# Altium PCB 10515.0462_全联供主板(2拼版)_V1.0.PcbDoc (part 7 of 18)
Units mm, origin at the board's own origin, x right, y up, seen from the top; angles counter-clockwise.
Board outline 282 x 198 mm, 2 copper layers (Top Layer, Bottom Layer); 716 components, 0 nets, 2364 pads, 1800 vias.
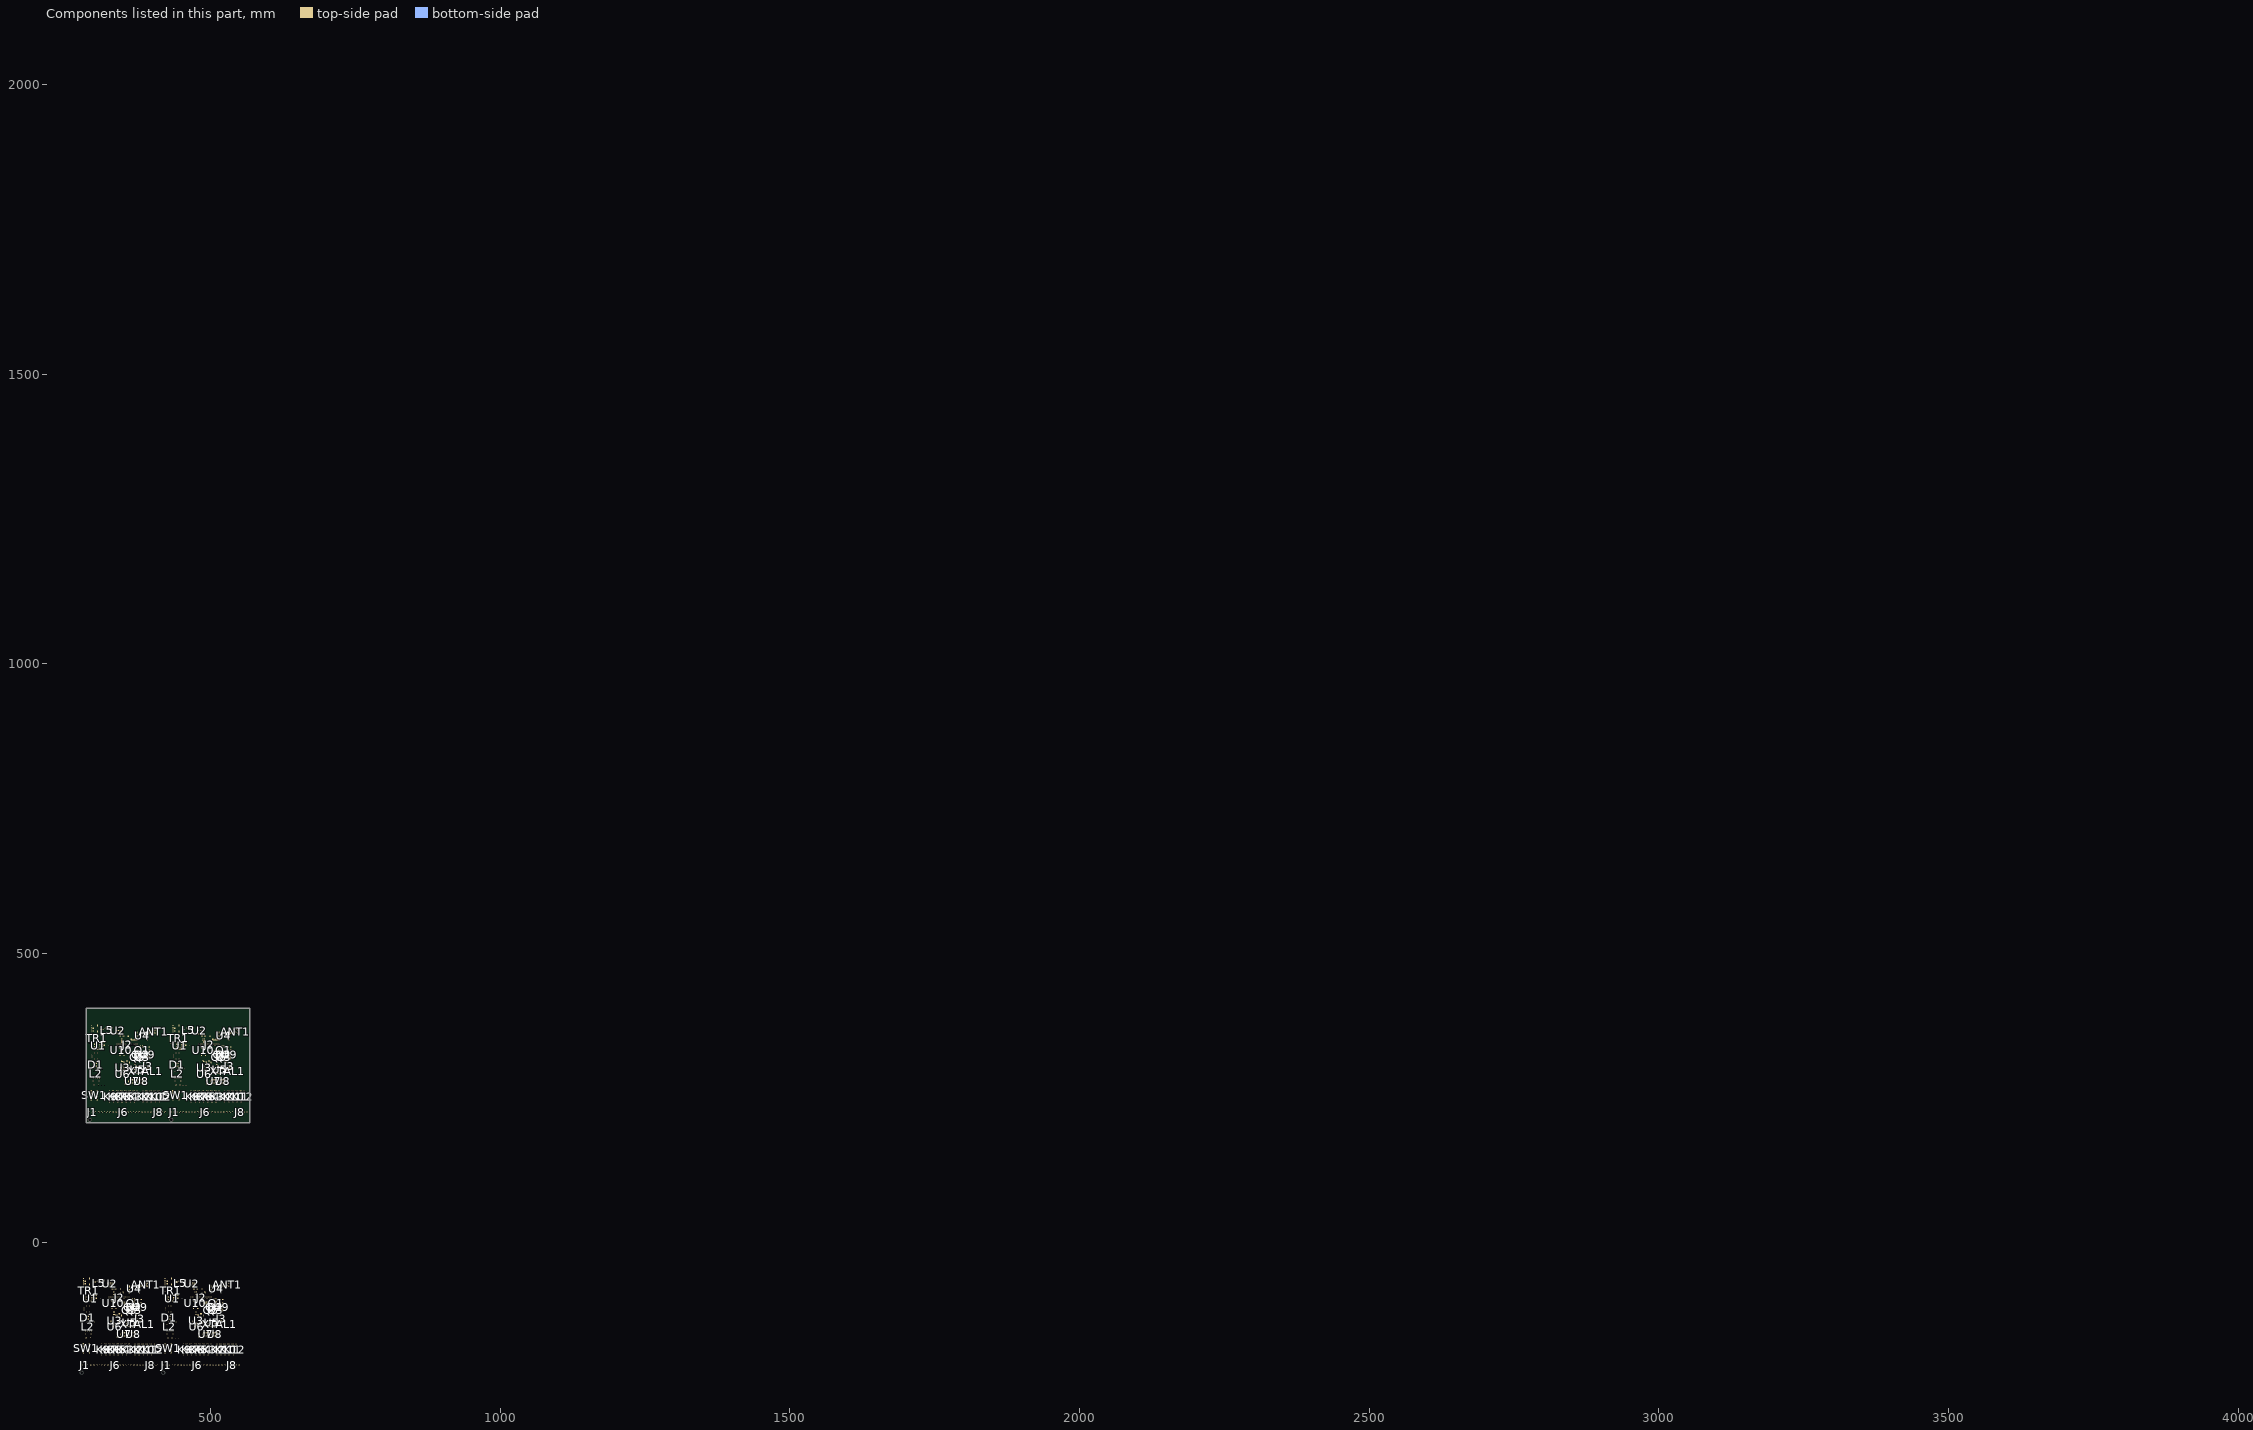
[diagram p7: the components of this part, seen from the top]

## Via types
v1: diameter 0.7, hole 0.4, Top Layer to Bottom Layer, tented both sides, 1800 vias

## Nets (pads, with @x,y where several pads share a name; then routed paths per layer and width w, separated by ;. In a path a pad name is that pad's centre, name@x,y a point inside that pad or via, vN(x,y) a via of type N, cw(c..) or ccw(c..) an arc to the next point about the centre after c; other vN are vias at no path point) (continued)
copper on no net: (continued)
  Top Layer w0.45: 390.197,261.97 390.197,263.712 ; 390.322,-173.798 ccw(c389.169,-172.645) 390.799,-172.645 ccw(c392.429,-172.645) 391.276,-173.798 ; v1@390.329,296.908 cw(c390.034,296.613) 390.452,296.613 ; 390.506,319.548 ccw(c389.632,320.423) v1@390.868,320.423 ; 390.592,304.283 ccw(c390.12,304.755) 390.676,305.125 ; 390.615,262.851 cw(c391.294,263.712) 390.197,263.712 ; 390.634,319.382 390.868,319.616 v1(390.868,320.491) 390.868,322.246 ; 390.672,331.157 ccw(c390.363,331.467) 390.801,331.467 ccw(c391.239,331.467) 390.929,331.157 ; 390.709,301.341 cw(c390.709,300.773) 391.111,301.175 ; 390.71,330.901 cw(c390.329,330.52) 390.868,330.52 ; 390.801,331.029 390.801,338.143 390.545,338.398 ; 390.868,328.342 390.868,330.961 ; v1@390.937,320.594 392.138,320.594 392.138,322.246 ; v1@390.957,320.403 cw(c391.419,319.941) 391.419,320.594 ; 391.047,302.632 cw(c390.406,301.992) 391.312,301.992 cw(c392.217,301.992) 391.577,302.632 ; 391.187,301.431 ccw(c390.886,301.732) 391.312,301.732 ; 391.277,301.303 391.312,301.338 ; 391.312,301.75 ccw(c391.762,301.75) 391.444,301.431 ; 391.312,302.838 391.312,301.338 ; 392.005,336.938 ccw(c390.386,338.558) 392.675,338.631 ; 392.183,319.382 393.731,319.382 ; 392.196,331.157 ccw(c391.887,331.467) 392.325,331.467 ccw(c392.763,331.467) 392.453,331.157 ; 392.311,319.254 cw(c392.621,318.944) 392.621,319.382 cw(c392.621,319.82) 392.311,319.51 ; 392.325,331.029 392.325,331.793 391.815,332.302 391.815,336.747 393.72,338.652 ; 392.74,337.673 ccw(c391.809,338.603) 393.125,338.646 ; 392.856,337.788 cw(c393.339,337.305) 393.339,337.988 ; 392.923,339.17 ccw(c392.012,340.303) 393.466,340.303 ; 392.928,301.303 393.318,301.303 394.912,302.897 394.912,305.078 395.144,305.31 ; 392.966,301.484 ccw(c392.966,302.771) 393.876,301.861 ; 393.303,333.969 ccw(c392.597,334.842) v1(393.72,334.842) ccw(c394.843,334.842) 394.137,333.969 ; 393.408,319.44 393.408,322.246 ; 393.408,320.638 ccw(c394.949,320.638) 393.86,319.548 ; 393.408,324.539 v1(393.408,326.841) ; 393.466,339.949 ccw(c394.635,339.949) 393.808,339.122 ; 393.603,319.254 ccw(c393.293,318.944) 393.293,319.382 ccw(c393.293,319.82) 393.603,319.51 ; 393.72,333.452 v1(393.72,334.842) ; 393.885,330.901 cw(c392.445,329.461) 394.482,329.461 ; 393.93,301.915 ccw(c392.949,302.897) 394.337,302.897 ; 393.976,331.029 394.482,330.523 394.482,326.206 v1(394.228,325.952) ; 394.003,330.848 cw(c393.972,330.339) 394.482,330.339 ; v1@394.139,326.041 ccw(c393.313,326.867) 394.482,326.867 ; 394.195,331.029 ccw(c394.725,331.029) 394.35,330.654 ; 394.204,331.219 cw(c393.532,330.547) 394.482,330.547 ; 394.647,303.162 ccw(c394.006,303.802) 394.912,303.802 ccw(c395.817,303.802) 395.177,303.162 ; 394.746,305.039 cw(c394.346,304.639) 394.912,304.639 ; 394.912,303.519 cw(c397.062,303.519) 395.541,305.039 ; 394.912,304.606 cw(c395.975,304.606) 395.223,305.358 ; 395.042,364.82 395.208,364.654 401.201,364.654 ; 395.311,364.538 cw(c395.59,364.259) 395.59,364.654 ; 395.311,364.795 ccw(c395.651,365.135) 395.651,364.654 ; 396.865,262.823 ccw(c395.961,263.832) 397.316,263.832 ; 397.316,261.97 397.316,263.832 ; 397.561,-173.798 ccw(c396.408,-172.645) 398.038,-172.645 ccw(c399.668,-172.645) 398.515,-173.798 ; 397.605,361.399 ccw(c396.26,360.49) v1@396.26,362.114 ; 397.605,362.828 cw(c396.26,363.738) v1@396.26,362.114 ; 397.766,262.823 cw(c398.671,263.832) 397.316,263.832 ; 397.978,361.651 ccw(c397.108,361.063) 397.108,362.114 ccw(c397.108,363.164) 397.978,362.576 ; 398.546,362.114 v1@396.26,362.114 ; 400.371,363.823 ccw(c398.365,361.817) 398.365,364.654 ccw(c398.365,367.49) 400.371,365.484 ; 400.689,364.141 ccw(c399.451,362.903) 399.451,364.654 ccw(c399.451,366.404) 400.689,365.166 ; 403.95,262.798 ccw(c402.798,263.95) 404.428,263.95 ccw(c406.057,263.95) 404.905,262.798 ; 411.189,262.798 ccw(c410.037,263.95) 411.667,263.95 ccw(c413.296,263.95) 412.144,262.798 ; 430.059,-97.823 430.059,-97.562 ; 430.059,-95.283 430.059,-94.895 ; 431.415,-99.768 ccw(c431.263,-99.478) 431.59,-99.478 ; 431.59,-100.099 431.59,-99.478 ; 431.677,-100.099 cw(c433.386,-100.099) 432.178,-98.891 ; 431.765,-99.768 cw(c431.917,-99.478) 431.59,-99.478 ; 432.127,-100.099 cw(c434.923,-100.099) 432.946,-98.123 ; 433.576,-99.834 ccw(c432.851,-99.11) 433.876,-99.11 ; 433.876,-99.972 433.876,-96.049 434.642,-95.283 436.155,-95.283 438.071,-95.283 438.448,-94.906 438.448,-93.763 439.464,-92.747 ; 433.876,-99.279 ccw(c434.662,-99.279) 434.106,-99.834 ; 436.155,-97.823 439.976,-97.823 ; 436.155,-94.013 433.753,-94.013 432.987,-94.779 432.987,-98.081 431.59,-99.478 ; 436.375,-90.056 ccw(c437.32,-89.112) 437.32,-90.447 ; 436.693,-89.738 ccw(c438.406,-88.025) 438.406,-90.447 ; 437.012,-89.42 ccw(c439.492,-86.939) 439.492,-90.447 ; 437.226,-90.447 440.48,-90.447 443.209,-90.447 ; 438.196,-97.823 ccw(c438.196,-95.198) 440.053,-97.054 ; 439.283,-97.823 ccw(c439.283,-96.284) 440.371,-97.372 ; 440.042,-93.001 ccw(c439.464,-93.532) 439.464,-92.747 ; 440.042,-92.494 cw(c439.464,-91.963) 439.464,-92.747 ; 440.053,-90.713 ccw(c439.413,-91.353) 439.413,-90.447 ccw(c439.413,-89.542) 440.053,-90.182 ; 440.48,-92.747 439.464,-92.747 ; 440.632,-90.447 ccw(c440.632,-87.582) 442.658,-89.608 ; 440.907,-90.713 cw(c441.547,-91.353) 441.547,-90.447 cw(c441.547,-89.542) 440.907,-90.182 ; 441.356,-90.447 cw(c441.356,-92.29) 442.658,-90.987 ; 441.494,-90.447 cw(c441.494,-92.639) 443.119,-91.169 ; 441.719,-90.447 ccw(c441.719,-88.668) 442.977,-89.926 ; 442.047,-90.447 ccw(c442.047,-89.355) 442.819,-90.128 ; v1(442.986,-81.687) 444.002,-82.703 445.78,-82.703 ; v1@443.191,-81.892 ccw(c443.621,-81.462) v1@443.621,-82.07 ; 443.494,-80.544 442.859,-80.544 442.605,-80.798 442.605,-82.068 443.24,-82.703 445.78,-82.703 ; 443.688,338.772 443.688,339.033 ; 443.688,341.312 443.688,341.7 ; v1@443.746,-82.195 ccw(c444.354,-82.195) 443.924,-82.625 ; 445.044,336.828 ccw(c444.892,337.117) 445.219,337.117 ccw(c445.545,337.117) 445.393,336.828 ; 445.219,336.496 445.219,337.117 446.616,338.514 446.616,341.816 447.382,342.582 449.784,342.582 ; 445.306,336.496 cw(c447.015,336.496) 445.806,337.705 ; 445.756,336.496 cw(c448.551,336.496) 446.575,338.473 ; 447.205,336.761 ccw(c446.48,337.486) 447.505,337.486 ; 447.505,336.623 447.505,340.546 448.271,341.312 449.784,341.312 451.7,341.312 452.077,341.689 452.077,342.832 453.093,343.848 ; 447.505,337.317 ccw(c448.291,337.317) 447.735,336.761 ; 449.784,338.772 453.605,338.772 ; 450.004,346.539 ccw(c450.948,347.484) 450.948,346.148 ; 450.322,346.857 ccw(c452.035,348.57) 452.035,346.148 ; 450.64,347.176 ccw(c453.121,349.656) 453.121,346.148 ; 450.855,346.148 454.109,346.148 456.838,346.148 ; 451.825,338.772 ccw(c451.825,341.398) 453.682,339.541 ; 452.194,-173.925 ccw(c451.041,-172.772) 452.671,-172.772 ccw(c454.301,-172.772) 453.148,-173.925 ; 452.671,-174.752 452.671,-172.123 455.72,-169.074 487.978,-169.074 488.613,-168.439 488.613,-166.153 488.613,-160.438 ; 452.912,338.772 ccw(c452.912,340.311) 454,339.223 ; 453.671,343.594 ccw(c453.093,343.063) 453.093,343.848 ; 453.671,344.102 cw(c453.093,344.633) 453.093,343.848 ; 453.682,345.883 ccw(c453.041,345.243) 453.041,346.148 ccw(c453.041,347.053) 453.682,346.413 ; 454.109,343.848 453.093,343.848 ; 454.261,346.148 ccw(c454.261,349.013) 456.287,346.987 ; 454.536,345.883 cw(c455.176,345.243) 455.176,346.148 cw(c455.176,347.053) 454.536,346.413 ; 454.985,346.148 cw(c454.985,344.306) 456.287,345.608 ; 455.123,346.148 cw(c455.123,343.956) 456.748,345.426 ; 455.348,346.148 ccw(c455.348,347.927) 456.605,346.669 ; 455.676,346.148 ccw(c455.676,347.24) 456.448,346.468 ; v1(456.615,354.908) 457.631,353.892 459.409,353.892 ; v1@456.82,354.704 ccw(c457.25,355.134) v1@457.25,354.525 ; 457.083,-83.846 455.94,-82.703 445.78,-82.703 ; 457.123,356.051 456.488,356.051 456.234,355.797 456.234,354.527 456.869,353.892 459.409,353.892 ; v1@457.375,354.4 ccw(c457.983,354.4) 457.553,353.97 ; 459.379,-173.925 ccw(c458.227,-172.772) 459.856,-172.772 ccw(c461.486,-172.772) 460.334,-173.925 ; 459.856,-174.752 459.856,-172.05 462.1,-169.806 488.897,-169.806 489.883,-168.82 489.883,-166.534 489.883,-160.438 ; 461.995,-71.781 462.544,-71.781 ; 462.29,-72.035 462.544,-71.781 ; 462.544,-71.831 cw(c463.391,-71.831) 462.932,-71.119 ; 462.63,-67.78 cw(c462.139,-68.272) 462.834,-68.272 ; 462.706,-69.111 ccw(c462.396,-68.802) 462.834,-68.802 ccw(c463.272,-68.802) 462.962,-69.111 ; 462.834,-71.781 462.925,-71.781 ; 462.834,-67.666 462.834,-69.278 463.198,-69.642 465.458,-69.642 ; 462.847,-70.942 465.458,-70.942 ; 462.962,-70.801 ccw(c463.304,-70.459) 463.304,-70.942 ; 462.962,-69.188 ccw(c464.06,-68.09) 464.06,-69.642 ; 462.979,-70.857 ccw(c463.814,-70.225) v1@463.814,-71.273 ; 463.772,-70.942 ccw(c463.772,-70.469) v1@464.107,-70.804 ; v1@464.08,-70.844 cw(c463.433,-70.571) 463.433,-71.273 ; v1(464.195,-70.892) v1@463.814,-71.273 ; v1@464.284,-70.804 ccw(c464.618,-70.469) 464.618,-70.942 ; 464.436,-67.717 v1(465.211,-67.717) ; 464.538,-67.524 ccw(c465.004,-67.058) v1@465.004,-67.717 ; 464.713,-72.76 cw(c464.403,-73.07) 464.841,-73.07 cw(c465.279,-73.07) 464.97,-72.76 ; 464.841,-75.022 ccw(c465.32,-75.022) 465.073,-75.432 ; 464.841,-74.225 ccw(c465.8,-74.225) 465.305,-75.047 ; 464.841,-73.429 ccw(c466.28,-73.429) 465.538,-74.661 ; 465.36,-96.285 cw(c464.93,-97.235) 465.973,-97.235 ; 465.499,-75.475 464.841,-74.818 464.841,-72.632 ccw(c466.76,-72.632) 465.77,-74.276 ; 465.545,-95.875 cw(c465.245,-96.538) 465.973,-96.538 ; 465.822,262.671 ccw(c464.67,263.823) 466.3,263.823 ccw(c467.929,263.823) 466.777,262.671 ; 465.973,-96.188 465.973,-97.181 ; 466.3,261.843 466.3,264.472 469.349,267.521 501.607,267.521 502.242,268.156 502.242,270.442 502.242,276.157 ; 466.474,-96.565 cw(c468.121,-98.212) 468.121,-95.882 ; 466.492,-72.632 467.901,-72.632 ; 466.539,-173.925 ccw(c465.386,-172.772) 467.016,-172.772 ccw(c468.645,-172.772) 467.493,-173.925 ; 466.659,-72.76 cw(c466.968,-73.07) 466.968,-72.632 cw(c466.968,-72.194) 466.659,-72.504 ; 466.804,-96.234 cw(c467.304,-96.735) 467.769,-96.201 ; 466.989,-129.312 465.973,-128.296 465.973,-97.181 ; 467.016,-174.752 467.016,-172.257 468.816,-170.456 490.025,-170.456 491.153,-169.328 491.153,-167.042 491.153,-160.438 ; 467.145,-95.893 cw(c467.622,-96.37) 468.064,-95.861 ; 467.242,-95.797 cw(c468.121,-96.675) 468.121,-95.432 ; 467.243,-95.795 465.973,-97.065 465.973,-97.181 ; 467.387,-72.632 ccw(c467.387,-72.102) 467.761,-72.477 ; 468.243,-136.468 469.848,-136.468 470.123,-136.193 v1(470.672,-136.193) ; 468.243,-134.817 469.786,-134.817 ; 468.371,-136.596 cw(c468.681,-136.906) 468.681,-136.468 cw(c468.681,-136.03) 468.371,-136.34 ; 468.371,-134.945 cw(c468.681,-135.255) 468.681,-134.817 cw(c468.681,-134.379) 468.371,-134.689 ; 469.362,-136.468 ccw(c469.362,-136.006) 469.689,-136.333 ; 469.362,-134.817 ccw(c469.362,-134.355) 469.689,-134.682 ; 469.396,-136.468 cw(c469.396,-136.882) 469.689,-136.589 ; 469.396,-134.817 cw(c469.396,-135.231) 469.689,-134.938 ; v1(469.656,-68.987) 470.412,-68.987 ; 469.849,-136.467 cw(c470.357,-136.975) v1@470.625,-136.309 ; 469.892,-134.923 472.294,-134.923 474.273,-134.923 474.58,-135.229 474.58,-138.086 ; v1@469.899,-68.987 cw(c469.899,-69.7) 470.403,-69.196 ; 469.945,-134.758 ccw(c470.343,-134.36) 470.343,-134.923 ; 469.966,-136.564 cw(c470.672,-137.049) v1(470.672,-136.193) ; 470.329,-145.584 472.364,-145.584 ; 470.448,-144.314 472.364,-144.314 478.46,-144.314 ; 470.452,-132.887 cw(c471.072,-132.887) v1@470.634,-132.448 ; v1@470.634,-132.272 ccw(c470.902,-132.004) 470.902,-132.383 ; 470.661,-92.718 ccw(c470.661,-91.422) 471.578,-92.339 ccw(c472.494,-93.255) 471.198,-93.255 cw(c473.722,-93.255) 471.937,-91.471 ; 470.712,352.749 469.569,353.892 459.409,353.892 ; 470.748,-93.255 cw(c472.185,-93.255) 471.169,-92.239 ; 471.561,-91.466 472.654,-90.373 473.238,-90.373 472.145,-91.466 ; 471.942,-91.466 470.661,-92.747 470.661,-93.255 472.45,-91.466 ; 471.959,-91.068 cw(c473.199,-92.309) 473.199,-90.554 ; 472.294,-136.193 v1(470.672,-136.193) ; 472.294,-133.653 470.463,-133.653 470.452,-133.641 470.452,-132.394 470.463,-132.383 472.294,-132.383 ; 472.364,-146.854 470.456,-146.854 470.325,-146.722 470.325,-143.42 470.702,-143.044 472.364,-143.044 474.258,-143.044 474.516,-142.785 474.516,-141.515 474.516,-140.708 474.736,-140.488 v1(477.403,-140.488) ; 472.381,-90.646 cw(c472.824,-91.089) 473.115,-90.534 ; 472.727,-90.3 cw(c473.199,-90.772) 473.199,-90.104 ; 472.863,-90.748 ccw(c472.488,-90.373) 473.018,-90.373 ; 473.008,262.671 ccw(c471.855,263.823) 473.485,263.823 ccw(c475.115,263.823) 473.962,262.671 ; 473.071,-90.501 ccw(c472.761,-90.811) 472.761,-90.373 ccw(c472.761,-89.935) 473.071,-90.245 ; 473.485,261.843 473.485,264.545 475.729,266.789 502.526,266.789 503.512,267.775 503.512,270.061 503.512,276.157 ; 473.786,-173.851 ccw(c473.253,-173.098) 474.175,-173.098 ; 474.175,-174.752 474.175,-173.098 ; 474.362,-131.053 cw(c474.053,-131.362) 474.491,-131.362 cw(c474.929,-131.362) 474.619,-131.053 ; 474.388,-141.644 cw(c474.078,-141.953) 474.516,-141.953 cw(c474.954,-141.953) 474.644,-141.644 ; 474.388,-141.387 ccw(c474.078,-141.077) 474.516,-141.077 ccw(c474.954,-141.077) 474.644,-141.387 ; 474.451,-137.958 ccw(c474.142,-137.648) 474.58,-137.648 ccw(c475.017,-137.648) 474.708,-137.958 ; v1(474.491,-134.13) 474.491,-131.051 ; 474.565,-173.851 cw(c475.098,-173.098) 474.175,-173.098 ; 475.624,364.814 476.173,364.814 ; 475.919,364.56 476.173,364.814 ; 476.013,-131.053 cw(c475.724,-131.342) 476.133,-131.342 ; 476.039,-141.644 cw(c475.729,-141.953) 476.167,-141.953 cw(c476.605,-141.953) 476.295,-141.644 ; 476.102,-137.958 ccw(c475.793,-137.648) 476.231,-137.648 ccw(c476.668,-137.648) 476.359,-137.958 ; 476.133,-131.383 cw(c476.6,-131.383) 476.27,-131.053 ; 476.133,-131.09 476.133,-131.957 476.559,-132.383 478.39,-132.383 ; 476.173,364.764 cw(c477.019,364.764) 476.561,365.476 ; 476.231,-138.086 476.231,-134.086 476.664,-133.653 478.39,-133.653 480.537,-133.653 480.993,-133.197 ; 476.259,368.815 cw(c475.767,368.323) 476.463,368.323 ; 476.333,-141.644 cw(c476.643,-141.953) 476.643,-141.515 cw(c476.643,-141.077) 476.333,-141.387 ; 476.335,367.484 ccw(c476.025,367.794) 476.463,367.794 ccw(c476.901,367.794) 476.591,367.484 ; 476.463,364.814 476.554,364.814 ; 476.463,368.93 476.463,367.318 476.827,366.953 479.087,366.953 ; 476.476,365.653 479.087,365.653 ; 476.591,365.795 ccw(c476.933,366.137) 476.933,365.653 ; 476.591,367.408 ccw(c477.688,368.505) 477.688,366.953 ; 476.607,365.738 ccw(c477.443,366.37) v1@477.443,365.322 ; 477.401,365.653 ccw(c477.401,366.127) v1@477.736,365.792 ; v1(477.694,-138.112) 481.07,-138.112 485.642,-138.112 ; v1@477.709,365.752 cw(c477.062,366.024) 477.062,365.322 ; v1(477.773,-141.515) 476.167,-141.515 476.167,-142.785 476.425,-143.044 478.46,-143.044 ; v1(477.824,365.703) v1@477.443,365.322 ; v1@477.912,365.792 ccw(c478.247,366.127) 478.247,365.653 ; 478.065,368.878 v1(478.84,368.878) ; 478.167,369.072 ccw(c478.633,369.538) v1@478.633,368.878 ; 478.342,363.835 cw(c478.032,363.525) 478.47,363.525 cw(c478.908,363.525) 478.598,363.835 ; 478.39,-136.193 480.853,-136.193 481.095,-136.435 482.517,-136.435 ; 478.39,-134.923 482.442,-134.923 482.517,-134.848 ; 478.47,361.574 ccw(c478.949,361.574) 478.702,361.163 ; 478.47,362.37 ccw(c479.429,362.37) 478.934,361.549 ; 478.47,363.167 ccw(c479.909,363.167) 479.166,361.934 ; 478.988,340.311 cw(c478.559,339.36) 479.602,339.36 ; 479.128,361.12 478.47,361.778 478.47,363.963 ccw(c480.389,363.963) 479.399,362.32 ; 479.174,340.721 cw(c478.874,340.058) 479.602,340.058 ; 479.547,-133.653 ccw(c479.547,-131.789) 480.865,-133.107 ; 479.602,340.408 479.602,339.414 ; 480.077,-136.193 cw(c480.077,-137.416) 480.942,-136.551 ; 480.103,340.031 cw(c481.75,338.384) 481.75,340.713 ; 480.121,363.963 481.529,363.963 ; 480.167,262.671 ccw(c479.015,263.823) 480.645,263.823 ccw(c482.274,263.823) 481.122,262.671 ; 480.288,363.835 cw(c480.597,363.525) 480.597,363.963 cw(c480.597,364.401) 480.288,364.092 ; 480.433,340.361 cw(c480.933,339.861) 481.397,340.395 ; 480.467,-134.923 ccw(c480.467,-134.36) 480.865,-134.758 ; 480.618,307.283 479.602,308.299 479.602,339.414 ; 480.618,-133.572 cw(c480.993,-133.946) 480.993,-133.416 ; 480.633,-133.653 ccw(c480.633,-132.875) 481.183,-133.425 ; 480.645,261.843 480.645,264.339 482.445,266.139 503.654,266.139 504.782,267.267 504.782,269.553 504.782,276.157 ; 480.774,340.702 cw(c481.251,340.226) 481.693,340.734 ; 480.871,340.799 cw(c481.75,339.92) 481.75,341.163 ; 480.872,340.8 479.602,339.53 479.602,339.414 ; 480.942,-138.24 ccw(c480.632,-138.55) 480.632,-138.112 ccw(c480.632,-137.674) 480.942,-137.984 ; 481.015,363.963 ccw(c481.015,364.493) 481.39,364.119 ; 481.111,-174.417 cw(c482.424,-174.331) 481.493,-173.4 ; 481.121,-134.758 ccw(c481.519,-134.36) 481.519,-134.923 ; 481.198,-138.24 cw(c481.508,-138.55) 481.508,-138.112 cw(c481.508,-137.674) 481.198,-137.984 ; 481.198,-136.551 cw(c481.477,-136.83) 481.477,-136.435 ; 481.198,-136.294 ccw(c481.539,-135.954) 481.539,-136.435 ; 481.335,-174.752 481.335,-173.558 482.898,-171.995 492.169,-171.995 493.693,-170.471 493.693,-168.185 493.693,-160.438 ; 481.56,-174.387 cw(c483.742,-174.244) 482.196,-172.698 ; 481.872,300.128 483.477,300.128 483.752,300.403 v1(484.301,300.403) ; 481.872,301.779 483.415,301.779 ; 481.991,-134.923 ccw(c481.991,-134.36) 482.389,-134.758 ; 482,299.999 cw(c482.31,299.69) 482.31,300.128 cw(c482.31,300.566) 482,300.256 ; 482,301.65 cw(c482.31,301.341) 482.31,301.779 cw(c482.31,302.217) 482,301.907 ; 482.009,-174.358 cw(c485.06,-174.158) 482.898,-171.996 ; 482.351,-136.564 ccw(c482.041,-136.873) 482.041,-136.435 ccw(c482.041,-135.997) 482.351,-136.307 ; 482.517,-133.197 v1(483.447,-133.197) ; 482.645,-133.325 cw(c482.955,-133.635) 482.955,-133.197 cw(c482.955,-132.759) 482.645,-133.069 ; 482.991,300.128 ccw(c482.991,300.59) 483.318,300.263 ; 482.991,301.779 ccw(c482.991,302.241) 483.318,301.914 ; 483.025,300.128 cw(c483.025,299.714) 483.318,300.006 ; 483.025,301.779 cw(c483.025,301.365) 483.318,301.657 ; v1(483.285,367.608) 484.041,367.608 ; 483.478,300.128 cw(c483.986,299.62) v1@484.254,300.287 ; 483.52,301.673 485.923,301.673 487.902,301.673 488.208,301.367 488.208,298.509 ; v1@483.528,367.608 cw(c483.528,366.896) 484.032,367.4 ; 483.574,301.838 ccw(c483.972,302.236) 483.972,301.673 ; 483.595,300.032 cw(c484.301,299.546) v1(484.301,300.403) ; 483.958,291.012 485.993,291.012 ; 484.077,292.282 485.993,292.282 492.089,292.282 ; 484.081,303.709 cw(c484.7,303.709) v1@484.262,304.147 ; 484.168,-136.435 487.102,-136.435 ; v1@484.262,304.324 ccw(c484.53,304.592) 484.53,304.213 ; 484.29,343.877 ccw(c484.29,345.174) 485.206,344.257 ccw(c486.123,343.34) 484.827,343.34 cw(c487.35,343.34) 485.566,345.125 ; 484.334,-136.564 cw(c484.644,-136.873) 484.644,-136.435 cw(c484.644,-135.997) 484.334,-136.307 ; 484.377,343.34 cw(c485.814,343.34) 484.798,344.356 ; 484.475,-80.259 cw(c483.152,-81.582) 485.023,-81.582 cw(c486.894,-81.582) 485.571,-80.259 ; 485.023,-86.711 485.628,-86.107 ; 485.023,-79.711 485.023,-83.719 485.468,-84.163 485.76,-84.456 490.661,-84.456 490.737,-84.379 500.054,-84.379 500.303,-84.13 ; 485.173,-136.435 ccw(c485.173,-135.954) 485.514,-136.294 ; 485.19,345.129 486.283,346.222 486.866,346.222 485.773,345.129 ; 485.235,-136.435 cw(c485.235,-136.83) 485.514,-136.551 ; 485.488,-158.635 486.683,-158.635 ; 485.514,-138.24 ccw(c485.204,-138.55) 485.204,-138.112 ccw(c485.204,-137.674) 485.514,-137.984 ; 485.571,345.129 484.29,343.848 484.29,343.34 486.079,345.129 ; 485.588,345.527 cw(c486.828,344.287) 486.828,346.041 ; 485.616,-158.763 cw(c485.926,-159.073) 485.926,-158.635 cw(c485.926,-158.197) 485.616,-158.507 ; 485.616,-157.112 cw(c485.926,-157.422) 485.926,-156.984 cw(c485.926,-156.546) 485.616,-156.856 ; 485.77,-136.551 cw(c486.049,-136.83) 486.049,-136.435 ; 485.77,-136.294 ccw(c486.111,-135.954) 486.111,-136.435 ; 485.923,300.403 v1(484.301,300.403) ; 485.923,302.943 484.092,302.943 484.081,302.954 484.081,304.202 484.092,304.213 485.923,304.213 ; 485.993,289.742 484.085,289.742 483.954,289.873 483.954,293.175 484.331,293.552 485.993,293.552 487.887,293.552 488.145,293.81 488.145,295.08 488.145,295.887 488.365,296.107 v1(491.032,296.107) ; 486.01,345.95 cw(c486.453,345.507) 486.744,346.062 ; 486.356,346.295 cw(c486.828,345.823) 486.828,346.491 ; 486.492,345.848 ccw(c486.117,346.222) 486.647,346.222 ; 486.7,346.094 ccw(c486.39,345.785) 486.39,346.222 ccw(c486.39,346.66) 486.7,346.351 ; 486.852,-158.804 cw(c485.967,-159.688) 487.218,-159.688 ; 486.986,-136.564 ccw(c486.676,-136.873) 486.676,-136.435 ccw(c486.676,-135.997) 486.986,-136.307 ; 487.343,-160.438 487.343,-159.295 486.683,-158.635 ; 487.343,-159.919 487.309,-159.885 487.309,-158.635 ; 487.343,-154.85 487.343,-156.236 ; 487.415,262.745 ccw(c486.882,263.498) 487.804,263.498 ; 487.463,-105.32 487.465,-105.318 ; 487.69,-156.984 487.343,-156.637 487.343,-156.236 ; 487.804,261.843 487.804,263.498 ; 487.991,305.543 cw(c487.681,305.233) 488.119,305.233 cw(c488.557,305.233) 488.248,305.543 ; 488.017,294.952 cw(c487.707,294.642) 488.145,294.642 cw(c488.583,294.642) 488.273,294.952 ; 488.017,295.208 ccw(c487.707,295.518) 488.145,295.518 ccw(c488.583,295.518) 488.273,295.208 ; 488.071,-86.107 492.034,-86.107 492.161,-85.98 ; 488.08,298.637 ccw(c487.77,298.947) 488.208,298.947 ccw(c488.646,298.947) 488.337,298.637 ; v1(488.119,302.466) 488.119,305.544 ; 488.194,262.745 cw(c488.726,263.498) 487.804,263.498 ; 488.495,-174.752 488.495,-173.765 489.502,-172.757 493.566,-172.757 494.963,-171.36 494.963,-169.074 494.963,-160.438 ; 488.71,-174.336 cw(c489.715,-174.03) 488.972,-173.288 ; 488.836,-86.107 ccw(c488.836,-85.644) 489.163,-85.971 ; 488.836,-84.456 ccw(c488.836,-83.993) 489.163,-84.32 ; 488.871,-86.107 cw(c488.871,-86.52) 489.163,-86.228 ; 488.871,-84.456 cw(c488.871,-84.869) 489.163,-84.577 ; 489.14,-174.205 cw(c490.527,-173.782) 489.502,-172.757 ; 489.419,-86.228 cw(c489.712,-86.52) 489.712,-86.107 ; 489.419,-85.971 ccw(c489.746,-85.644) 489.746,-86.107 ; 489.419,-84.577 cw(c489.712,-84.869) 489.712,-84.456 ; 489.419,-84.32 ccw(c489.746,-83.993) 489.746,-84.456 ; 489.642,305.543 cw(c489.353,305.254) 489.762,305.254 ; 489.668,294.952 cw(c489.358,294.642) 489.796,294.642 cw(c490.234,294.642) 489.924,294.952 ; 489.731,298.637 ccw(c489.421,298.947) 489.859,298.947 ccw(c490.297,298.947) 489.988,298.637 ; 489.762,305.213 cw(c490.229,305.213) 489.899,305.543 ; 489.762,305.505 489.762,304.639 490.188,304.213 492.019,304.213 ; 489.859,298.509 489.859,302.51 490.293,302.943 492.019,302.943 494.166,302.943 494.622,303.399 ; 489.962,294.952 cw(c490.272,294.642) 490.272,295.08 cw(c490.272,295.518) 489.962,295.208 ; 490.533,-86.235 ccw(c490.223,-86.545) 490.223,-86.107 ccw(c490.223,-85.669) 490.533,-85.978 ; 490.533,-84.584 ccw(c490.223,-84.894) 490.223,-84.456 ccw(c490.223,-84.018) 490.533,-84.327 ; 490.789,-86.235 cw(c491.099,-86.545) 491.099,-86.107 cw(c491.099,-85.669) 490.789,-85.978 ; 490.789,-84.546 cw(c491.191,-84.947) 491.191,-84.379 ; 490.899,-143.143 490.901,-143.141 491.754,-143.141 492.727,-143.141 ; 491.027,-143.272 cw(c491.343,-143.587) 491.343,-143.141 ; 491.027,-143.015 ccw(c491.331,-142.711) 491.331,-143.141 ; v1(491.323,298.484) 494.699,298.484 499.271,298.484 ; 491.378,-86.107 ccw(c491.378,-85.235) 491.994,-85.851 ; v1(491.401,295.08) 489.796,295.08 489.796,293.81 490.054,293.552 492.089,293.552 ; v1(491.895,-141.49) 492.657,-141.49 ; 492.019,300.403 494.481,300.403 494.724,300.16 496.146,300.16 ; 492.019,301.673 496.071,301.673 496.146,301.748 ; 492.423,-160.438 492.423,-167.677 492.423,-169.963 491.28,-171.106 476.167,-171.106 474.175,-173.098 ; 492.599,-143.269 ccw(c492.289,-143.579) 492.289,-143.141 ccw(c492.289,-142.703) 492.599,-143.013 ; 492.599,-141.618 ccw(c492.289,-141.928) 492.289,-141.49 ccw(c492.289,-141.052) 492.599,-141.362 ; 492.727,-141.49 493.419,-141.49 v1@493.888,-141.021 ; 492.855,-141.618 cw(c493.165,-141.928) 493.165,-141.49 cw(c493.165,-141.052) 492.855,-141.362 ; 493.141,-96.175 cw(c492.225,-97.092) 493.521,-97.092 cw(c494.817,-97.092) 493.901,-96.175 ; v1@493.151,-133.126 v1@493.151,-127.28 ; 493.151,-127.888 cw(c493.886,-127.888) v1@493.367,-127.368 ; 493.176,302.943 ccw(c493.176,304.807) 494.494,303.489 ; 493.521,-95.795 493.521,-98.821 493.913,-99.213 497.977,-99.213 498.298,-99.534 498.298,-107.281 498.624,-107.606 500.15,-107.606 500.15,-107.65 ; 493.546,-141.363 ccw(c492.96,-140.777) v1@493.788,-140.747 ; 493.705,300.403 cw(c493.705,299.179) 494.571,300.045 ; 493.812,-85.98 493.962,-86.13 500.303,-86.13 ; 493.978,-85.851 ccw(c494.651,-85.179) 494.651,-86.13 ; 494.095,301.673 ccw(c494.095,302.236) 494.494,301.838 ; 494.247,303.024 cw(c494.622,302.649) 494.622,303.179 ; 494.262,302.943 ccw(c494.262,303.72) 494.812,303.171 ; 494.448,-105.32 494.448,-105.318 ; 494.571,298.355 ccw(c494.261,298.046) 494.261,298.484 ccw(c494.261,298.922) 494.571,298.612 ; 494.739,262.179 cw(c496.053,262.265) 495.122,263.195 ; 494.75,301.838 ccw(c495.148,302.236) 495.148,301.673 ; 494.801,-86.13 ccw(c494.801,-85.482) 495.259,-85.94 ; 494.827,298.355 cw(c495.137,298.046) 495.137,298.484 cw(c495.137,298.922) 494.827,298.612 ; 494.827,300.045 cw(c495.106,299.765) 495.106,300.16 ; 494.827,300.301 ccw(c495.167,300.641) 495.167,300.16 ; 494.964,261.843 494.964,263.037 496.527,264.6 505.798,264.6 507.322,266.124 507.322,268.41 507.322,276.157 ; 495.12,-173.925 ccw(c492.432,-171.237) 496.233,-171.237 ; 495.188,262.208 cw(c497.371,262.351) 495.824,263.898 ; 495.259,-84.508 ccw(c494.949,-84.817) 494.949,-84.379 ccw(c494.949,-83.941) 495.259,-84.251 ; 495.438,-174.243 ccw(c493.518,-172.323) 496.233,-172.323 ; 495.515,-85.94 ccw(c495.974,-85.482) 495.974,-86.13 ; 495.515,-84.508 cw(c495.825,-84.817) 495.825,-84.379 cw(c495.825,-83.941) 495.515,-84.251 ; 495.619,301.673 ccw(c495.619,302.236) 496.018,301.838 ; 495.637,262.238 cw(c498.689,262.437) 496.527,264.6 ; 495.756,-174.561 ccw(c494.605,-173.41) 496.233,-173.41 ; 495.931,-128.218 ccw(c495.591,-127.877) 496.072,-127.877 ; 495.965,-129.626 ccw(c495.645,-129.306) 496.098,-129.306 ; 495.969,-128.474 cw(c495.66,-128.784) 496.098,-128.784 cw(c496.535,-128.784) 496.226,-128.474 ; 495.979,300.032 ccw(c495.67,299.722) 495.67,300.16 ccw(c495.67,300.598) 495.979,300.288 ; 496.072,-128.321 v1(496.072,-127.28) ; 496.072,-127.939 ccw(c496.467,-127.939) 496.188,-128.218 ; 496.098,-129.721 496.098,-128.346 ; 496.098,-129.327 ccw(c496.521,-129.327) 496.222,-129.626 ; 496.099,-103.669 496.111,-103.658 v1(496.961,-103.658) ; 496.101,-101.941 v1(496.945,-101.941) ; 496.146,303.399 v1(497.076,303.399) ; 496.198,-86.13 ccw(c496.198,-85.482) 496.656,-85.94 ; 496.233,-171.83 496.233,-171.222 ; 496.233,-160.438 496.233,-171.222 ; 496.265,-103.798 cw(c496.603,-104.135) 496.603,-103.658 ; 496.265,-103.541 ccw(c496.548,-103.259) 496.548,-103.658 ; 496.268,-102.07 cw(c496.577,-102.379) 496.577,-101.941 cw(c496.577,-101.503) 496.268,-101.813 ; 496.274,303.27 cw(c496.584,302.961) 496.584,303.399 cw(c496.584,303.837) 496.274,303.527 ; 496.503,-116.209 496.551,-116.162 ; 496.656,-84.508 ccw(c496.346,-84.817) 496.346,-84.379 ccw(c496.346,-83.941) 496.656,-84.251 ; 496.912,-85.94 ccw(c497.371,-85.482) 497.371,-86.13 ; 496.912,-84.508 cw(c497.222,-84.817) 497.222,-84.379 cw(c497.222,-83.941) 496.912,-84.251 ; 497.595,-86.13 ccw(c497.595,-85.482) 498.053,-85.94 ; 497.616,-129.626 ccw(c497.296,-129.306) 497.749,-129.306 ; 497.62,-128.474 cw(c497.311,-128.784) 497.749,-128.784 cw(c498.186,-128.784) 497.877,-128.474 ; 497.749,-129.721 497.749,-128.346 497.985,-128.11 v1(498.612,-128.11) ccw(c498.612,-128.953) 497.933,-128.453 ; 497.749,-129.327 ccw(c498.172,-129.327) 497.873,-129.626 ; 497.797,300.16 500.73,300.16 ; 497.963,300.032 cw(c498.273,299.722) 498.273,300.16 cw(c498.273,300.598) 497.963,300.288 ; 498.053,-84.508 ccw(c497.743,-84.817) 497.743,-84.379 ccw(c497.743,-83.941) 498.053,-84.251 ; 498.104,356.336 cw(c496.781,355.013) 498.652,355.013 cw(c500.523,355.013) 499.2,356.336 ; 498.309,-85.94 ccw(c498.768,-85.482) 498.768,-86.13 ; 498.309,-84.508 cw(c498.619,-84.817) 498.619,-84.379 cw(c498.619,-83.941) 498.309,-84.251 ; 498.587,-84.379 ccw(c498.587,-82.864) 499.659,-83.936 ; 498.652,349.884 499.256,350.489 ; 498.652,356.884 498.652,352.876 499.096,352.432 499.388,352.14 504.29,352.14 504.366,352.216 513.682,352.216 513.932,352.465 ; 498.802,300.16 ccw(c498.802,300.641) 499.143,300.301 ; 498.863,300.16 cw(c498.863,299.765) 499.143,300.045 ; 499.117,277.96 500.311,277.96 ; 499.143,298.355 ccw(c498.833,298.046) 498.833,298.484 ccw(c498.833,298.922) 499.143,298.612 ; 499.245,277.832 cw(c499.555,277.523) 499.555,277.96 cw(c499.555,278.398) 499.245,278.089 ; 499.245,279.483 cw(c499.555,279.174) 499.555,279.611 cw(c499.555,280.049) 499.245,279.74 ; 499.399,300.045 cw(c499.678,299.765) 499.678,300.16 ; 499.399,300.301 ccw(c499.739,300.641) 499.739,300.16 ; 499.659,-86.324 ccw(c499.189,-86.794) 499.189,-86.13 ccw(c499.189,-85.466) 499.659,-85.936 ; 499.779,-107.978 ccw(c498.883,-108.874) 498.883,-107.606 ccw(c498.883,-106.339) 499.779,-107.235 ; 499.893,-114.591 499.998,-114.591 500.131,-114.459 ; 500.48,277.791 cw(c499.596,276.907) 500.847,276.907 ; 500.615,300.032 ccw(c500.305,299.722) 500.305,300.16 ccw(c500.305,300.598) 500.615,300.288 ; 500.854,-158.763 ccw(c500.544,-159.073) 500.544,-158.635 ccw(c500.544,-158.197) 500.854,-158.507 ; 500.854,-157.112 ccw(c500.544,-157.422) 500.544,-156.984 ccw(c500.544,-156.546) 500.854,-156.856 ; 500.972,276.157 500.972,277.3 500.311,277.96 ; 500.972,276.676 500.938,276.71 500.938,277.96 ; 500.972,281.745 500.972,280.359 ; 501.092,331.275 501.094,331.277 ; 501.11,-157.112 cw(c501.42,-157.422) 501.42,-156.984 cw(c501.42,-156.546) 501.11,-156.856 ; 501.319,279.611 500.972,279.959 500.972,280.359 ; 501.7,350.489 505.662,350.489 505.789,350.616 ; 501.758,-112.781 501.78,-112.803 ; 502.124,261.843 502.124,262.831 503.131,263.838 507.195,263.838 508.592,265.235 508.592,267.521 508.592,276.157 ; 502.129,-158.587 cw(c501.028,-159.688) 502.585,-159.688 ; 502.339,262.259 cw(c503.343,262.565) 502.601,263.308 ; 502.465,350.489 ccw(c502.465,350.951) 502.792,350.624 ; 502.465,352.14 ccw(c502.465,352.602) 502.792,352.275 ; 502.499,350.489 cw(c502.499,350.076) 502.792,350.368 ; 502.499,352.14 cw(c502.499,351.727) 502.792,352.019 ; 502.7,-159.688 501.646,-158.635 501.406,-158.635 ; 502.71,-160.565 502.71,-160.438 502.71,-159.168 502.177,-158.635 501.406,-158.635 ; 502.71,-156.236 501.962,-156.984 501.787,-156.984 ; 502.71,-154.977 502.71,-156.628 ; 502.769,262.39 cw(c504.156,262.813) 503.131,263.838 ; 503.048,350.368 cw(c503.34,350.076) 503.34,350.489 ; 503.048,350.624 ccw(c503.375,350.951) 503.375,350.489 ; 503.048,352.019 cw(c503.34,351.727) 503.34,352.14 ; 503.048,352.275 ccw(c503.375,352.602) 503.375,352.14 ; v1(503.692,-117.755) 503.692,-116.975 503.917,-116.75 503.917,-116.052 504.234,-115.734 505.377,-115.734 505.568,-115.544 505.568,-114.591 ; v1@503.692,-117.638 cw(c504.766,-117.638) 504.007,-116.879 ; 503.725,-150.127 cw(c503.415,-150.437) 503.853,-150.437 cw(c504.291,-150.437) 503.981,-150.127 ; 503.788,-116.622 ccw(c503.479,-116.312) 503.917,-116.312 ccw(c504.354,-116.312) 504.045,-116.622 ; v1(503.853,-150.913) 503.853,-149.961 ; 503.917,-119.117 503.917,-118.909 ; 503.98,-160.565 503.98,-169.582 503.98,-171.868 504.488,-172.376 509.822,-172.376 510.456,-173.01 ; 504.162,350.361 ccw(c503.852,350.051) 503.852,350.489 ccw(c503.852,350.927) 504.162,350.617 ; 504.162,352.012 ccw(c503.852,351.702) 503.852,352.14 ccw(c503.852,352.578) 504.162,352.268 ; 504.418,350.361 cw(c504.728,350.051) 504.728,350.489 cw(c504.728,350.927) 504.418,350.617 ; 504.418,352.05 cw(c504.82,351.648) 504.82,352.216 ; 504.528,293.452 504.53,293.454 505.383,293.454 506.356,293.454 ; 504.656,293.324 cw(c504.971,293.009) 504.971,293.454 ; 504.656,293.58 ccw(c504.96,293.885) 504.96,293.454 ; 505.007,350.489 ccw(c505.007,351.36) 505.623,350.744 ; 505.225,-146.168 cw(c504.937,-146.465) 505.352,-146.465 ; 505.25,-160.565 505.25,-168.932 505.25,-171.218 505.758,-171.726 516.411,-171.726 517.568,-172.883 ; 505.352,-146.467 cw(c505.701,-146.467) 505.496,-146.184 ; 505.352,-146.037 505.352,-146.465 ; 505.439,-114.72 cw(c505.13,-115.029) 505.568,-115.029 cw(c506.005,-115.029) 505.696,-114.72 ; 505.478,-146.168 ccw(c505.766,-146.465) 505.352,-146.465 ; v1(505.524,295.105) 506.286,295.105 ; 505.571,-146.042 ccw(c507.033,-146.079) v1@505.999,-147.113 ; 505.803,-112.969 cw(c505.803,-113.959) 506.503,-113.259 ; 505.803,-112.559 v1@506.994,-113.751 ; 506.052,276.157 506.052,268.918 506.052,266.632 504.909,265.489 489.796,265.489 487.804,263.498 ; v1(506.105,-144.425) 507.003,-145.322 507.003,-146.037 ; 506.15,-112.623 ccw(c506.833,-112.623) 506.35,-113.106 ; 506.228,293.326 ccw(c505.918,293.017) 505.918,293.454 ccw(c505.918,293.892) 506.228,293.583 ; 506.228,294.977 ccw(c505.918,294.668) 505.918,295.105 ccw(c505.918,295.543) 506.228,295.234 ; v1(506.232,-147.346) 505.352,-146.465 ; v1(506.232,-120.041) 511.058,-120.041 511.727,-119.372 v1(511.727,-117.12) 511.727,-116.179 ; 506.356,295.105 507.048,295.105 v1@507.516,295.574 ; 506.484,294.977 cw(c506.794,294.668) 506.794,295.105 cw(c506.794,295.543) 506.484,295.234 ; 506.52,-160.565 506.52,-168.282 506.52,-170.568 507.028,-171.076 523,-171.076 524.687,-172.763 ; 506.77,340.42 cw(c505.853,339.504) 507.15,339.504 cw(c508.446,339.504) 507.529,340.42 ; v1@506.78,303.469 v1@506.78,309.315 ; 506.78,308.707 cw(c507.515,308.707) v1@506.995,309.227 ; 506.846,-113.602 cw(c506.517,-113.931) v1@506.982,-113.931 ; 506.874,-145.909 ccw(c506.565,-145.599) 507.003,-145.599 ccw(c507.441,-145.599) 507.131,-145.909 ; 507.15,340.8 507.15,337.775 507.542,337.382 511.606,337.382 511.927,337.061 511.927,329.314 512.252,328.989 513.779,328.989 513.779,328.945 ; 507.175,295.232 ccw(c506.589,295.818) v1@507.417,295.849 ; 507.44,350.616 507.591,350.465 513.932,350.465 ; 507.607,350.744 ccw(c508.279,351.417) 508.279,350.465 ; 507.79,-160.565 507.79,-167.505 507.79,-169.791 508.425,-170.426 530.71,-170.426 531.799,-171.516 531.799,-174.625 ; 508.044,-117.131 508.044,-117.449 509.505,-118.909 ; 508.077,331.275 508.077,331.277 ; 508.391,-117.195 ccw(c509.84,-117.195) 508.815,-118.22 ; 508.429,350.465 ccw(c508.429,351.113) 508.888,350.655 ; 508.748,262.671 ccw(c506.061,265.358) 509.862,265.358 ; 508.888,352.088 ccw(c508.578,351.778) 508.578,352.216 ccw(c508.578,352.654) 508.888,352.344 ; 509.044,-114.631 509.148,-114.528 ; 509.044,-110.469 cw(c509.044,-111.459) 509.744,-110.759 cw(c510.444,-110.059) 509.454,-110.059 ; 509.044,-110.059 510.263,-111.278 511.41,-111.278 ; 509.06,-160.565 509.06,-166.661 509.06,-168.947 509.889,-169.776 537.426,-169.776 539.038,-171.389 539.038,-174.625 ; 509.067,262.353 ccw(c507.147,264.272) 509.862,264.272 ; 509.13,-118.535 cw(c508.755,-118.909) 509.285,-118.909 ; 509.144,350.655 ccw(c509.602,351.113) 509.602,350.465 ; 509.144,352.088 cw(c509.454,351.778) 509.454,352.216 cw(c509.454,352.654) 509.144,352.344 ; 509.3,-98.197 516.011,-98.197 517.916,-98.197 ; 509.3,-95.657 520.202,-95.657 520.837,-96.292 520.837,-97.943 ; 509.385,262.034 ccw(c508.234,263.186) 509.862,263.186 ; 509.56,308.378 ccw(c509.22,308.718) 509.701,308.718 ; 509.594,306.969 ccw(c509.274,307.289) 509.726,307.289 ; 509.598,308.121 cw(c509.288,307.812) 509.726,307.812 cw(c510.164,307.812) 509.855,308.121 ; 509.671,-98.568 cw(c510.567,-99.464) 510.567,-98.197 cw(c510.567,-96.93) 509.671,-97.826 ; 509.671,-96.028 cw(c510.567,-96.924) 510.567,-95.657 cw(c510.567,-94.39) 509.671,-95.286 ; 509.701,308.275 v1(509.701,309.315) ; 509.701,308.657 ccw(c510.095,308.657) 509.816,308.378 ; 509.726,306.875 509.726,308.249 ; 509.726,307.269 ccw(c510.15,307.269) 509.85,306.969 ; 509.728,332.926 509.739,332.937 v1(510.59,332.937) ; 509.73,334.654 v1(510.574,334.654) ; 509.826,350.465 ccw(c509.826,351.113) 510.285,350.655 ; 509.862,264.765 509.862,265.373 ; 509.862,276.157 509.862,265.373 ; 509.894,332.798 cw(c510.231,332.461) 510.231,332.937 ; 509.894,333.054 ccw(c510.176,333.336) 510.176,332.937 ; 509.897,334.526 cw(c510.206,334.216) 510.206,334.654 cw(c510.206,335.092) 509.897,334.782 ; 509.994,-112.559 509.994,-113.135 510.169,-113.31 v1(510.931,-113.31) ; 510.08,-173.714 ccw(c509.609,-173.01) 510.456,-173.01 ; 510.132,320.386 510.179,320.434 ; 510.169,-103.306 cw(c510.169,-104.296) 510.869,-103.596 ; 510.169,-102.896 511.727,-104.454 511.727,-109.944 ; 510.28,-133.286 v1@510.28,-127.28 ; 510.28,-132.503 ccw(c511.152,-132.503) 510.535,-133.119 ; 510.285,352.088 ccw(c509.975,351.778) 509.975,352.216 ccw(c509.975,352.654) 510.285,352.344 ; 510.456,-174.625 510.456,-173.01 ; 510.516,-102.959 ccw(c511.199,-102.959) 510.716,-103.443 ; 510.541,350.655 ccw(c510.999,351.113) 510.999,350.465 ; 510.541,352.088 cw(c510.851,351.778) 510.851,352.216 cw(c510.851,352.654) 510.541,352.344 ; 510.615,-111.278 cw(c510.615,-112.67) 511.599,-111.686 ; 510.832,-173.714 cw(c511.303,-173.01) 510.456,-173.01 ; 511.223,350.465 ccw(c511.223,351.113) 511.682,350.655 ; 511.245,306.969 ccw(c510.925,307.289) 511.377,307.289 ; 511.249,308.121 cw(c510.939,307.812) 511.377,307.812 cw(c511.815,307.812) 511.506,308.121 ; 511.377,306.875 511.377,308.249 511.614,308.486 v1(512.241,308.486) ccw(c512.241,307.643) 511.562,308.142 ; 511.377,307.269 ccw(c511.801,307.269) 511.501,306.969 ; 511.599,-116.345 cw(c511.289,-116.655) 511.727,-116.655 cw(c512.165,-116.655) 511.855,-116.345 ; 511.599,-109.778 ccw(c511.289,-109.468) 511.727,-109.468 ccw(c512.165,-109.468) 511.855,-109.778 ; 511.682,352.088 ccw(c511.372,351.778) 511.372,352.216 ccw(c511.372,352.654) 511.682,352.344 ; 511.938,350.655 ccw(c512.396,351.113) 512.396,350.465 ; 511.938,352.088 cw(c512.248,351.778) 512.248,352.216 cw(c512.248,352.654) 511.938,352.344 ; 512.216,352.216 ccw(c512.216,353.731) 513.287,352.66 ; 512.362,-139.293 513.979,-139.293 514.37,-138.902 514.37,-137.463 514.82,-137.013 ; 512.49,-139.421 cw(c512.8,-139.731) 512.8,-139.293 cw(c512.8,-138.855) 512.49,-139.165 ; 512.884,-139.293 ccw(c512.884,-137.541) 514.123,-138.78 ; 513.287,350.271 ccw(c512.818,349.802) 512.818,350.465 ccw(c512.818,351.129) 513.287,350.66 ; 513.408,328.618 ccw(c512.512,327.722) 512.512,328.989 ccw(c512.512,330.257) 513.408,329.36 ; 513.522,322.004 513.627,322.004 513.76,322.137 ; 513.668,-98.197 ccw(c513.668,-95.727) 515.415,-97.473 ; 514.123,-141.775 cw(c513.157,-142.74) 514.522,-142.74 ; 514.123,-138.53 ccw(c513.525,-137.932) 514.37,-137.932 ccw(c515.215,-137.932) 514.618,-138.53 ; 514.37,-141.402 514.522,-141.555 514.522,-143.27 514.522,-144.057 514.709,-144.243 517.442,-144.243 517.823,-143.862 517.823,-139.633 v1(517.789,-139.599) 517.092,-138.902 ; 514.37,-138.445 cw(c516.213,-138.445) 514.91,-137.142 ; 514.37,-137.623 cw(c514.798,-137.623) 514.786,-137.195 ; 514.37,-137.358 cw(c515.126,-137.358) 514.592,-136.823 ; 514.394,-143.398 cw(c514.084,-143.708) 514.522,-143.708 cw(c514.96,-143.708) 514.651,-143.398 ; 514.394,-143.142 ccw(c514.084,-142.832) 514.522,-142.832 ccw(c514.96,-142.832) 514.651,-143.142 ; 514.445,-137.388 ccw(c514.07,-137.013) 514.6,-137.013 ; 514.483,277.832 ccw(c514.173,277.523) 514.173,277.96 ccw(c514.173,278.398) 514.483,278.089 ; 514.483,279.483 ccw(c514.173,279.174) 514.173,279.611 ccw(c514.173,280.049) 514.483,279.74 ; v1(514.597,-110.406) 515.453,-110.406 ; 514.739,279.483 cw(c515.049,279.174) 515.049,279.611 cw(c515.049,280.049) 514.739,279.74 ; 514.754,-98.197 ccw(c514.754,-96.813) 515.733,-97.792 ; 514.894,-98.197 cw(c514.894,-98.933) 515.415,-98.413 ; 515.122,-133.52 ccw(c514.813,-133.21) 515.251,-133.21 ccw(c515.689,-133.21) 515.379,-133.52 ; 515.251,-133.648 515.251,-132.994 515.63,-132.614 517.662,-132.614 518.515,-131.761 518.515,-131.285 ; 515.325,-110.534 ccw(c515.015,-110.844) 515.015,-110.406 ccw(c515.015,-109.968) 515.325,-110.278 ; 515.386,323.814 515.408,323.792 ; 515.453,-110.279 515.809,-110.635 v1(519.884,-110.635) v1@520.011,-110.635 ; 515.581,-110.316 ccw(c516.351,-109.546) 516.351,-110.635 ; 515.758,278.008 cw(c514.657,276.907) 516.214,276.907 ; 515.796,-103.613 cw(c514.662,-104.746) 516.265,-104.746 cw(c517.868,-104.746) 516.735,-103.613 ; 515.815,-102.655 ccw(c514.864,-101.626) v1(516.265,-101.626) ccw(c517.666,-101.626) 516.716,-102.655 ; 516.045,-143.142 ccw(c515.735,-142.832) 516.173,-142.832 ccw(c516.611,-142.832) 516.302,-143.142 ; 516.123,-138.53 ccw(c515.525,-137.932) 516.37,-137.932 ccw(c517.215,-137.932) 516.618,-138.53 ; 516.173,-143.27 516.173,-141.599 516.37,-141.402 ; 516.173,-142.847 cw(c517.69,-142.847) 516.618,-141.775 ; 516.265,-105.311 516.265,-103.143 v1(516.265,-101.626) ; 516.265,-104.603 ccw(c517.446,-104.603) 516.611,-105.438 ; 516.305,-138.951 cw(c516.722,-139.435) 517.173,-138.983 ; 516.329,-117.047 ccw(c514.783,-115.501) 516.97,-115.501 ; 516.328,276.907 515.275,277.96 515.035,277.96 ; 516.339,276.03 516.339,276.157 516.339,277.427 515.805,277.96 515.035,277.96 ; 516.339,280.359 515.591,279.611 515.416,279.611 ; 516.339,281.618 516.339,279.967 ; 516.36,-138.928 cw(c516.504,-140.386) 517.54,-139.35 ; 516.37,-137.602 cw(c517.021,-137.602) 516.561,-137.142 ; 516.457,-117.213 516.97,-116.701 516.97,-114.349 ; 516.457,-116.994 ccw(c516.457,-116.464) 516.832,-116.839 ; 516.471,-137.013 516.37,-137.114 516.37,-138.902 517.092,-138.902 ; 516.599,-139.292 cw(c517.039,-139.803) 517.516,-139.326 ; 516.645,-139.119 cw(c517.092,-139.472) 517.092,-138.902 ; 516.645,-138.685 ccw(c517.092,-138.332) 517.092,-138.902 ; 516.647,-117.365 ccw(c515.869,-116.587) 516.97,-116.587 ; 516.773,-135.164 ccw(c516.464,-134.854) 516.902,-134.854 ccw(c517.34,-134.854) 517.03,-135.164 ; 516.773,-133.777 cw(c516.464,-134.086) 516.902,-134.086 cw(c517.34,-134.086) 517.03,-133.777 ; 516.902,-133.648 516.902,-135.254 518.679,-135.254 518.683,-135.258 ; 516.97,-110.635 516.97,-108.253 ; 517.03,-135.421 cw(c517.432,-135.822) 517.432,-135.254 ; 517.116,-98.413 cw(c517.636,-98.933) 517.636,-98.197 ; 517.15,-173.745 ccw(c516.471,-172.883) 517.568,-172.883 ; 517.277,-97.735 ccw(c517.916,-97.524) 517.916,-98.197 ; v1(517.321,318.84) 517.321,319.621 517.545,319.845 517.545,320.544 517.863,320.861 519.006,320.861 519.196,321.052 519.196,322.004 ; v1@517.321,318.957 cw(c518.395,318.957) 517.635,319.717 ; 517.354,286.468 cw(c517.044,286.159) 517.482,286.159 cw(c517.92,286.159) 517.61,286.468 ; 517.417,319.973 ccw(c517.107,320.283) 517.545,320.283 ccw(c517.983,320.283) 517.674,319.973 ; v1(517.482,285.682) 517.482,286.635 ; 517.545,317.479 517.545,317.686 ; 517.568,-174.625 517.568,-172.883 ; 517.609,276.03 517.609,267.013 517.609,264.727 518.117,264.219 523.451,264.219 524.085,263.585 ; v1@517.701,-139.687 cw(c517.406,-139.983) 517.823,-139.983 ; 517.877,-117.047 ccw(c517.003,-116.173) v1@518.24,-116.173 ; 517.963,-132.313 ccw(c517.491,-131.841) 518.047,-131.47 ; 517.986,-173.745 cw(c518.665,-172.883) 517.568,-172.883 ; 518.006,-117.213 518.24,-116.98 v1(518.24,-116.104) 518.24,-114.349 ; 518.044,-105.438 ccw(c517.734,-105.129) 518.172,-105.129 ccw(c518.61,-105.129) 518.3,-105.438 ; 518.08,-135.254 cw(c518.08,-135.822) 518.482,-135.421 ; 518.082,-105.695 cw(c517.701,-106.076) 518.24,-106.076 ; 518.172,-105.567 518.172,-98.453 517.916,-98.197 ; 518.24,-108.253 518.24,-105.634 ; v1@518.309,-116.001 519.51,-116.001 519.51,-114.349 ; v1@518.328,-116.192 cw(c518.79,-116.654) 518.79,-116.001 ; 518.418,-133.964 cw(c517.778,-134.604) 518.683,-134.604 cw(c519.588,-134.604) 518.948,-133.964 ; 518.558,-135.164 ccw(c518.257,-134.863) 518.683,-134.863 ; 518.649,-135.292 518.683,-135.258 ; 518.683,-134.846 ccw(c519.133,-134.846) 518.815,-135.164 ; 518.683,-133.757 518.683,-135.258 ; 518.854,290.428 cw(c518.566,290.13) 518.98,290.13 ; 518.879,276.03 518.879,267.663 518.879,265.377 519.387,264.869 530.04,264.869 531.197,263.712 ; 518.98,290.128 cw(c519.329,290.128) 519.125,290.411 ; 518.98,290.558 518.98,290.13 ; 519.068,321.876 cw(c518.758,321.566) 519.196,321.566 cw(c519.634,321.566) 519.325,321.876 ; 519.107,290.428 ccw(c519.395,290.13) 518.98,290.13 ; 519.2,290.554 ccw(c520.662,290.517) v1@519.628,289.483 ; 519.377,-99.657 ccw(c517.757,-98.038) 520.046,-97.964 ; 519.432,323.626 cw(c519.432,322.636) 520.132,323.336 ; 519.432,324.036 v1@520.623,322.845 ; 519.554,-117.213 521.103,-117.213 ; 519.568,-105.438 ccw(c519.258,-105.129) 519.696,-105.129 ccw(c520.134,-105.129) 519.824,-105.438 ; 519.682,-117.342 cw(c519.992,-117.651) 519.992,-117.213 cw(c519.992,-116.775) 519.682,-117.085 ; 519.696,-105.567 519.696,-104.803 519.186,-104.293 519.186,-99.848 521.091,-97.943 ; v1(519.734,292.17) 520.631,291.273 520.631,290.558 ; 519.778,323.973 ccw(c520.462,323.973) 519.978,323.489 ; v1(519.861,289.249) 518.98,290.13 ; v1(519.861,316.554) 524.687,316.554 525.356,317.223 v1(525.356,319.475) 525.356,320.417 ; 520.111,-98.923 ccw(c519.181,-97.992) 520.496,-97.95 ; 520.149,276.03 520.149,268.313 520.149,266.027 520.657,265.519 536.629,265.519 538.316,263.832 ; 520.227,-98.807 cw(c520.71,-99.29) 520.71,-98.607 ; 520.294,-97.426 ccw(c519.383,-96.292) 520.837,-96.292 ; 520.3,-135.292 520.689,-135.292 522.283,-133.698 522.283,-131.517 522.515,-131.285 ; 520.338,-135.111 ccw(c520.338,-133.825) 521.247,-134.734 ; 520.475,322.993 cw(c520.146,322.664) v1@520.611,322.664 ; 520.503,290.686 ccw(c520.193,290.996) 520.631,290.996 ccw(c521.069,290.996) 520.76,290.686 ; 520.674,-102.626 ccw(c519.968,-101.753) v1(521.091,-101.753) ccw(c522.214,-101.753) 521.508,-102.626 ; 520.78,-117.155 520.78,-114.349 ; 520.78,-115.958 ccw(c522.32,-115.958) 521.231,-117.047 ; 520.78,-112.057 v1(520.78,-109.754) ; 520.837,-96.647 ccw(c522.007,-96.647) 521.18,-97.473 ; 520.974,-117.342 ccw(c520.665,-117.651) 520.665,-117.213 ccw(c520.665,-116.775) 520.974,-117.085 ; 521.091,-103.143 v1(521.091,-101.753) ; 521.257,-105.695 cw(c519.817,-107.135) 521.853,-107.135 ; 521.301,-134.68 ccw(c520.32,-133.698) 521.708,-133.698 ; 521.347,-105.567 521.853,-106.073 521.853,-110.389 v1(521.599,-110.643) ; 521.374,-105.748 cw(c521.344,-106.256) 521.853,-106.256 ; 521.419,276.03 521.419,269.09 521.419,266.804 522.054,266.169 544.338,266.169 545.428,265.08 545.428,261.97 ; v1@521.511,-110.555 ccw(c520.684,-109.728) 521.853,-109.728 ; 521.566,-105.567 ccw(c522.096,-105.567) 521.722,-105.941 ; 521.575,-105.377 cw(c520.903,-106.048) 521.853,-106.048 ; 521.673,319.464 521.673,319.147 523.133,317.686 ; 522.018,-133.433 ccw(c521.378,-132.793) 522.283,-132.793 ccw(c523.188,-132.793) 522.548,-133.433 ; 522.019,319.401 ccw(c523.469,319.401) 522.444,318.375 ; 522.117,-131.556 cw(c521.717,-131.956) 522.283,-131.956 ; 522.283,-133.076 cw(c524.433,-133.076) 522.913,-131.556 ; 522.283,-131.99 cw(c523.346,-131.99) 522.594,-131.238 ; 522.413,-71.776 522.579,-71.942 528.573,-71.942 ; 522.673,321.964 522.776,322.068 ; 522.673,326.126 cw(c522.673,325.136) 523.373,325.836 cw(c524.073,326.536) 523.083,326.536 ; 522.673,326.536 523.891,325.317 525.038,325.317 ; 522.682,-72.057 cw(c522.961,-72.336) 522.961,-71.942 ; 522.682,-71.801 ccw(c523.022,-71.461) 523.022,-71.942 ; 522.689,276.03 522.689,269.934 522.689,267.648 523.518,266.819 551.054,266.819 552.667,265.207 552.667,261.97 ; 522.759,318.061 cw(c522.384,317.686) 522.914,317.686 ; 522.928,338.398 529.64,338.398 531.545,338.398 ; 522.928,340.938 533.831,340.938 534.466,340.303 534.466,338.652 ; 523.3,338.027 cw(c524.196,337.131) 524.196,338.398 cw(c524.196,339.666) 523.3,338.77 ; 523.3,340.567 cw(c524.196,339.671) 524.196,340.938 cw(c524.196,342.206) 523.3,341.31 ; 523.623,324.036 523.623,323.461 523.798,323.285 v1(524.56,323.285) ; 523.709,262.881 ccw(c523.238,263.585) 524.085,263.585 ; 523.798,333.289 cw(c523.798,332.3) 524.498,333 ; 523.798,333.699 525.356,332.142 525.356,326.651 ; 523.909,303.31 v1@523.909,309.315 ; 523.909,304.092 ccw(c524.78,304.092) 524.164,303.476 ; 524.085,261.97 524.085,263.585 ; 524.144,333.636 ccw(c524.828,333.636) 524.345,333.153 ; 524.236,-173.772 ccw(c523.332,-172.764) 524.687,-172.764 ; 524.243,325.317 cw(c524.243,323.926) 525.228,324.91 ; 524.46,262.881 cw(c524.932,263.585) 524.085,263.585 ; 524.687,-174.625 524.687,-172.763 ; 524.977,-75.196 ccw(c523.631,-76.106) v1@523.631,-74.482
